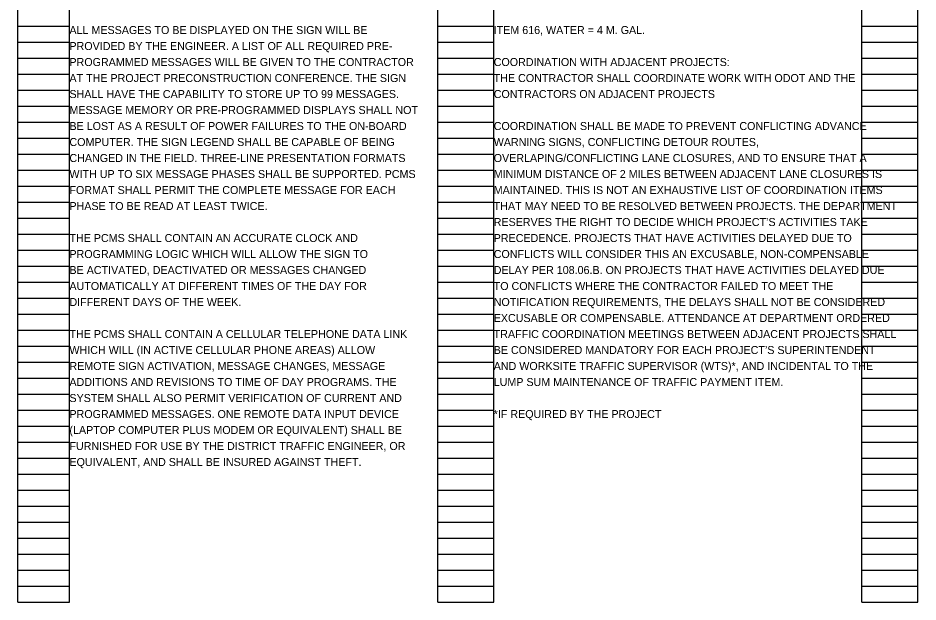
# Model space of a CAD drawing. Extents: x 51924.2 to 51956.2, y 31431.6 to 31530.7.
# Drawn here: x 51925.71 to 51941.45, y 31471.11 to 31481.33 of the extents above; entities that cross this region are included whole.
import ezdxf

# ---------------------------------------------------------------- set-up
doc = ezdxf.new("R2010")
doc.units = 0
doc.layers.add('SH_Data', color=7, linetype='Continuous')
doc.layers.add('SH_Text', color=7, linetype='Continuous')

msp = doc.modelspace()

# ---------------------------------------------------------------- linework, layer by layer
at = {"layer": 'SH_Data'}
for p, q in [((51925.708, 31471.11), (51925.708, 31491.27)), ((51926.608, 31471.11), (51926.608, 31491.27)), ((51933.048, 31471.11), (51933.048, 31491.27)), ((51934.028, 31471.11), (51934.028, 31491.27)), ((51940.468, 31471.11), (51940.468, 31491.27)), ((51941.448, 31471.11), (51941.448, 31491.27)), ((51925.708, 31481.19), (51926.608, 31481.19)), ((51933.048, 31481.19), (51934.028, 31481.19)), ((51940.468, 31481.19), (51941.448, 31481.19)), ((51925.708, 31480.91), (51926.608, 31480.91)), ((51933.048, 31480.91), (51934.028, 31480.91)), ((51940.468, 31480.91), (51941.448, 31480.91)), ((51925.708, 31480.63), (51926.608, 31480.63)), ((51933.048, 31480.63), (51934.028, 31480.63)), ((51940.468, 31480.63), (51941.448, 31480.63)), ((51925.708, 31480.35), (51926.608, 31480.35)), ((51933.048, 31480.35), (51934.028, 31480.35)), ((51940.468, 31480.35), (51941.448, 31480.35)), ((51925.708, 31480.07), (51926.608, 31480.07)), ((51933.048, 31480.07), (51934.028, 31480.07)), ((51940.468, 31480.07), (51941.448, 31480.07)), ((51925.708, 31479.79), (51926.608, 31479.79)), ((51933.048, 31479.79), (51934.028, 31479.79)), ((51940.468, 31479.79), (51941.448, 31479.79)), ((51925.708, 31479.51), (51926.608, 31479.51)), ((51933.048, 31479.51), (51934.028, 31479.51)), ((51940.468, 31479.51), (51941.448, 31479.51)), ((51925.708, 31479.23), (51926.608, 31479.23)), ((51933.048, 31479.23), (51934.028, 31479.23)), ((51940.468, 31479.23), (51941.448, 31479.23)), ((51925.708, 31478.95), (51926.608, 31478.95)), ((51933.048, 31478.95), (51934.028, 31478.95)), ((51940.468, 31478.95), (51941.448, 31478.95)), ((51925.708, 31478.67), (51926.608, 31478.67)), ((51933.048, 31478.67), (51934.028, 31478.67)), ((51940.468, 31478.67), (51941.448, 31478.67)), ((51925.708, 31478.39), (51926.608, 31478.39)), ((51933.048, 31478.39), (51934.028, 31478.39)), ((51940.468, 31478.39), (51941.448, 31478.39)), ((51925.708, 31478.11), (51926.608, 31478.11)), ((51933.048, 31478.11), (51934.028, 31478.11)), ((51940.468, 31478.11), (51941.448, 31478.11)), ((51925.708, 31477.83), (51926.608, 31477.83)), ((51933.048, 31477.83), (51934.028, 31477.83)), ((51940.468, 31477.83), (51941.448, 31477.83)), ((51925.708, 31477.55), (51926.608, 31477.55)), ((51933.048, 31477.55), (51934.028, 31477.55)), ((51940.468, 31477.55), (51941.448, 31477.55)), ((51925.708, 31477.27), (51926.608, 31477.27)), ((51933.048, 31477.27), (51934.028, 31477.27)), ((51940.468, 31477.27), (51941.448, 31477.27)), ((51925.708, 31476.99), (51926.608, 31476.99)), ((51933.048, 31476.99), (51934.028, 31476.99)), ((51940.468, 31476.99), (51941.448, 31476.99)), ((51925.708, 31476.71), (51926.608, 31476.71)), ((51933.048, 31476.71), (51934.028, 31476.71)), ((51940.468, 31476.71), (51941.448, 31476.71)), ((51925.708, 31476.43), (51926.608, 31476.43)), ((51933.048, 31476.43), (51934.028, 31476.43)), ((51940.468, 31476.43), (51941.448, 31476.43)), ((51925.708, 31476.15), (51926.608, 31476.15)), ((51933.048, 31476.15), (51934.028, 31476.15)), ((51940.468, 31476.15), (51941.448, 31476.15)), ((51925.708, 31475.87), (51926.608, 31475.87)), ((51933.048, 31475.87), (51934.028, 31475.87)), ((51940.468, 31475.87), (51941.448, 31475.87)), ((51925.708, 31475.59), (51926.608, 31475.59)), ((51933.048, 31475.59), (51934.028, 31475.59)), ((51940.468, 31475.59), (51941.448, 31475.59)), ((51925.708, 31475.31), (51926.608, 31475.31)), ((51933.048, 31475.31), (51934.028, 31475.31)), ((51940.468, 31475.31), (51941.448, 31475.31)), ((51925.708, 31475.03), (51926.608, 31475.03)), ((51933.048, 31475.03), (51934.028, 31475.03)), ((51940.468, 31475.03), (51941.448, 31475.03)), ((51925.708, 31474.75), (51926.608, 31474.75)), ((51933.048, 31474.75), (51934.028, 31474.75)), ((51940.468, 31474.75), (51941.448, 31474.75)), ((51925.708, 31474.47), (51926.608, 31474.47)), ((51933.048, 31474.47), (51934.028, 31474.47)), ((51940.468, 31474.47), (51941.448, 31474.47)), ((51925.708, 31474.19), (51926.608, 31474.19)), ((51933.048, 31474.19), (51934.028, 31474.19)), ((51940.468, 31474.19), (51941.448, 31474.19)), ((51925.708, 31473.91), (51926.608, 31473.91)), ((51933.048, 31473.91), (51934.028, 31473.91)), ((51940.468, 31473.91), (51941.448, 31473.91)), ((51925.708, 31473.63), (51926.608, 31473.63)), ((51933.048, 31473.63), (51934.028, 31473.63)), ((51940.468, 31473.63), (51941.448, 31473.63)), ((51925.708, 31473.35), (51926.608, 31473.35)), ((51933.048, 31473.35), (51934.028, 31473.35)), ((51940.468, 31473.35), (51941.448, 31473.35)), ((51925.708, 31473.07), (51926.608, 31473.07)), ((51933.048, 31473.07), (51934.028, 31473.07)), ((51940.468, 31473.07), (51941.448, 31473.07)), ((51925.708, 31472.79), (51926.608, 31472.79)), ((51933.048, 31472.79), (51934.028, 31472.79)), ((51940.468, 31472.79), (51941.448, 31472.79)), ((51925.708, 31472.51), (51926.608, 31472.51)), ((51933.048, 31472.51), (51934.028, 31472.51)), ((51940.468, 31472.51), (51941.448, 31472.51)), ((51925.708, 31472.23), (51926.608, 31472.23)), ((51933.048, 31472.23), (51934.028, 31472.23)), ((51940.468, 31472.23), (51941.448, 31472.23)), ((51925.708, 31471.95), (51926.608, 31471.95)), ((51933.048, 31471.95), (51934.028, 31471.95)), ((51940.468, 31471.95), (51941.448, 31471.95)), ((51925.708, 31471.67), (51926.608, 31471.67)), ((51933.048, 31471.67), (51934.028, 31471.67)), ((51940.468, 31471.67), (51941.448, 31471.67)), ((51925.708, 31471.39), (51926.608, 31471.39)), ((51933.048, 31471.39), (51934.028, 31471.39)), ((51940.468, 31471.39), (51941.448, 31471.39)), ((51925.708, 31471.11), (51926.608, 31471.11)), ((51933.048, 31471.11), (51934.028, 31471.11)), ((51940.468, 31471.11), (51941.448, 31471.11))]:
    msp.add_line(p, q, dxfattribs=at)

# ---------------------------------------------------------------- texts
at = {"layer": 'SH_Text'}
for s, p in [('ALL MESSAGES TO BE DISPLAYED ON THE SIGN WILL BE', (51926.608, 31481.05)), ('ITEM 616, WATER = 4 M. GAL.  ', (51934.028, 31481.05)), ('PROVIDED BY THE ENGINEER. A LIST OF ALL REQUIRED PRE-', (51926.608, 31480.77)), ('PROGRAMMED MESSAGES WILL BE GIVEN TO THE CONTRACTOR', (51926.608, 31480.49)), ('COORDINATION WITH ADJACENT PROJECTS:', (51934.028, 31480.49)), ('AT THE PROJECT PRECONSTRUCTION CONFERENCE. THE SIGN', (51926.608, 31480.21)), ('THE CONTRACTOR SHALL COORDINATE WORK WITH ODOT AND THE ', (51934.028, 31480.21)), ('SHALL HAVE THE CAPABILITY TO STORE UP TO 99 MESSAGES.', (51926.608, 31479.93)), ('CONTRACTORS ON ADJACENT PROJECTS', (51934.028, 31479.93)), ('.', (51937.587, 31479.93)), ('MESSAGE MEMORY OR PRE-PROGRAMMED DISPLAYS SHALL NOT', (51926.608, 31479.65)), ('BE LOST AS A RESULT OF POWER FAILURES TO THE ON-BOARD', (51926.608, 31479.37)), ('COORDINATION SHALL BE MADE TO PREVENT CONFLICTING ADVANCE ', (51934.028, 31479.37)), ('COMPUTER. THE SIGN LEGEND SHALL BE CAPABLE OF BEING', (51926.608, 31479.09)), ('WARNING SIGNS, CONFLICTING DETOUR ROUTES, ', (51934.028, 31479.09)), ('CHANGED IN THE FIELD. THREE-LINE PRESENTATION FORMATS', (51926.608, 31478.81)), ('OVERLAPING/CONFLICTING LANE CLOSURES, AND TO ENSURE THAT A ', (51934.028, 31478.81)), ('WITH UP TO SIX MESSAGE PHASES SHALL BE SUPPORTED. PCMS', (51926.608, 31478.53)), ('MINIMUM DISTANCE OF 2 MILES BETWEEN ADJACENT LANE CLOSURES IS ', (51934.028, 31478.53)), ('FORMAT SHALL PERMIT THE COMPLETE MESSAGE FOR EACH', (51926.608, 31478.25)), ('MAINTAINED. THIS IS NOT AN EXHAUSTIVE LIST OF COORDINATION ITEMS ', (51934.028, 31478.25)), ('PHASE TO BE READ AT LEAST TWICE.', (51926.608, 31477.97)), ('THAT MAY NEED TO BE RESOLVED BETWEEN PROJECTS. THE DEPARTMENT ', (51934.028, 31477.97)), ('RESERVES THE RIGHT TO DECIDE WHICH PROJECT’S ACTIVITIES TAKE ', (51934.028, 31477.69)), ('THE PCMS SHALL CONTAIN AN ACCURATE CLOCK AND', (51926.608, 31477.41)), ('PRECEDENCE. PROJECTS THAT HAVE ACTIVITIES DELAYED DUE TO ', (51934.028, 31477.41)), ('PROGRAMMING LOGIC WHICH WILL ALLOW THE SIGN TO', (51926.608, 31477.13)), ('CONFLICTS WILL CONSIDER THIS AN EXCUSABLE, NON-COMPENSABLE ', (51934.028, 31477.13)), ('BE ACTIVATED, DEACTIVATED OR MESSAGES CHANGED', (51926.608, 31476.85)), ('DELAY PER 108.06.B. ON PROJECTS THAT HAVE ACTIVITIES DELAYED DUE ', (51934.028, 31476.85)), ('AUTOMATICALLY AT DIFFERENT TIMES OF THE DAY FOR', (51926.608, 31476.57)), ('TO CONFLICTS WHERE THE CONTRACTOR FAILED TO MEET THE ', (51934.028, 31476.57)), ('DIFFERENT DAYS OF THE WEEK.', (51926.608, 31476.29)), ('NOTIFICATION REQUIREMENTS, THE DELAYS SHALL NOT BE CONSIDERED ', (51934.028, 31476.29)), ('EXCUSABLE OR COMPENSABLE. ATTENDANCE AT DEPARTMENT ORDERED ', (51934.028, 31476.01)), ('THE PCMS SHALL CONTAIN A CELLULAR TELEPHONE DATA LINK', (51926.608, 31475.73)), ('TRAFFIC COORDINATION MEETINGS BETWEEN ADJACENT PROJECTS SHALL ', (51934.028, 31475.73)), ('WHICH WILL (IN ACTIVE CELLULAR PHONE AREAS) ALLOW', (51926.608, 31475.45)), ('BE CONSIDERED MANDATORY FOR EACH PROJECT’S SUPERINTENDENT ', (51934.028, 31475.45)), ('REMOTE SIGN ACTIVATION, MESSAGE CHANGES, MESSAGE', (51926.608, 31475.17)), ('AND WORKSITE TRAFFIC SUPERVISOR (WTS)*, AND INCIDENTAL TO THE ', (51934.028, 31475.17)), ('ADDITIONS AND REVISIONS TO TIME OF DAY PROGRAMS. THE', (51926.608, 31474.89)), ('LUMP SUM MAINTENANCE OF TRAFFIC PAYMENT ITEM.', (51934.028, 31474.89)), ('SYSTEM SHALL ALSO PERMIT VERIFICATION OF CURRENT AND', (51926.608, 31474.61)), ('PROGRAMMED MESSAGES. ONE REMOTE DATA INPUT DEVICE', (51926.608, 31474.33)), ('*IF REQUIRED BY THE PROJECT', (51934.028, 31474.33)), ('(LAPTOP COMPUTER PLUS MODEM OR EQUIVALENT) SHALL BE', (51926.608, 31474.05)), ('FURNISHED FOR USE BY THE DISTRICT TRAFFIC ENGINEER, OR', (51926.608, 31473.77)), ('EQUIVALENT, AND SHALL BE INSURED AGAINST THEFT.', (51926.608, 31473.49))]:
    msp.add_text(s, height=0.14, dxfattribs=at).set_placement(p)

doc.saveas('drawing.dxf')
